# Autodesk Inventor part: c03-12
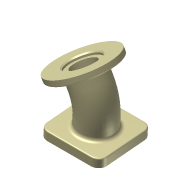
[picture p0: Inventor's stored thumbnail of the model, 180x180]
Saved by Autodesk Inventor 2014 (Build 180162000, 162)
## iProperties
Created: 2011-11
Part Number: c03-12
Material: Iron, Cast
Document SubType Name: Modeling
Designer: Thom Tremblay
Density: 7.25 g/cm^3
Mass: 1087.5 g
Surface Area: 260 cm^2
Volume: 150 cm^3
Appearance: Nylon 6
Author: Thom Tremblay
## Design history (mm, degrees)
sketch "Sketch1"
  geometry: L1 (50, -50)-(-50, -50); L2 (-50, -50)-(-50, 50); L3 (-50, 50)-(50, 50); L4 (50, 50)-(50, -50); C1 r 20 at (0, 0); C2 r 30 at (0, 0); 3 further points
  constraints: 8 end point, 2 centre point, 2 coincident, 2 midpoint, 2 parallel, 2 perpendicular, 1 horizontal, 1 horizontal alignment, 1 vertical alignment
  dimensions: "d0" = 100 distance of L2.end L3.end; "d3" = 40 diameter of C1; "d4" = 10 radial gap between concentric circles of C2 C1
extrude "Extrusion1" new body sketch "Sketch1" distance "d1" = 15; taper "d2" = 0 deg
sketch "Sketch2"
  geometry: L1 (0, 0)-(0, 30); L2 (12.794, 77.746)-(27.794, 103.727); A1 r 95.493 centre (95.493, 30) between (12.794, 77.746) and (0, 30)
  constraints: 4 end point, 2 point on circle, 2 tangent, 1 centre point, 1 vertical
  dimensions: "d5" = 30 distance of L1.start L1.end; "d7" = 50 dimension on A1; "d9" = 30 distance of L2.start L2.end; "d10" = 30 deg angle of L2 L1
sketch "Sketch3"
  geometry: L1 (12.794, 77.746)-(27.794, 103.727) reference; L2 (27.794, 103.727)-(75.425, 76.227); L3 (75.425, 76.227)-(70.425, 67.567); L4 (70.425, 67.567)-(22.794, 95.067); L5 (22.794, 95.067)-(27.794, 103.727); 2 further points
  constraints: 8 end point, 2 parallel, 2 perpendicular
  dimensions: "d11" = 110 diameter of L3 L5; "d13" = 10 distance between parallel lines of L2 L4
revolve "Revolution1" sketch "Sketch3" stored, may be unused: angle "d14" = 90 deg
sweep "Sweep1" dims "d15" = 0
sweep "Sweep2" dims "d16" = 0
sketch "Sketch4"
  geometry: C1 r 55 at (0, 0) reference; C2 r 27.5 at (0, 0); 1 further point
  constraints: 1 centre point, 1 coincident
  dimensions: "d17" = 55 diameter of C2
extrude "Extrusion2" cut sketch "Sketch4" distance "d18" = 5; taper "d19" = 0 deg
fillet "Fillet1" dims "d20" = 14
fillet "Fillet2" dims "d21" = 6, "d22" = 2
chamfer "Chamfer1" distance "d23" = 2; stored, may be unused: second distance "d24" = 2, angle "d25" = 45 deg
chamfer "Chamfer2" distance "d26" = 2; stored, may be unused: second distance "d27" = 4, angle "d28" = 45 deg
body "Solid1"
